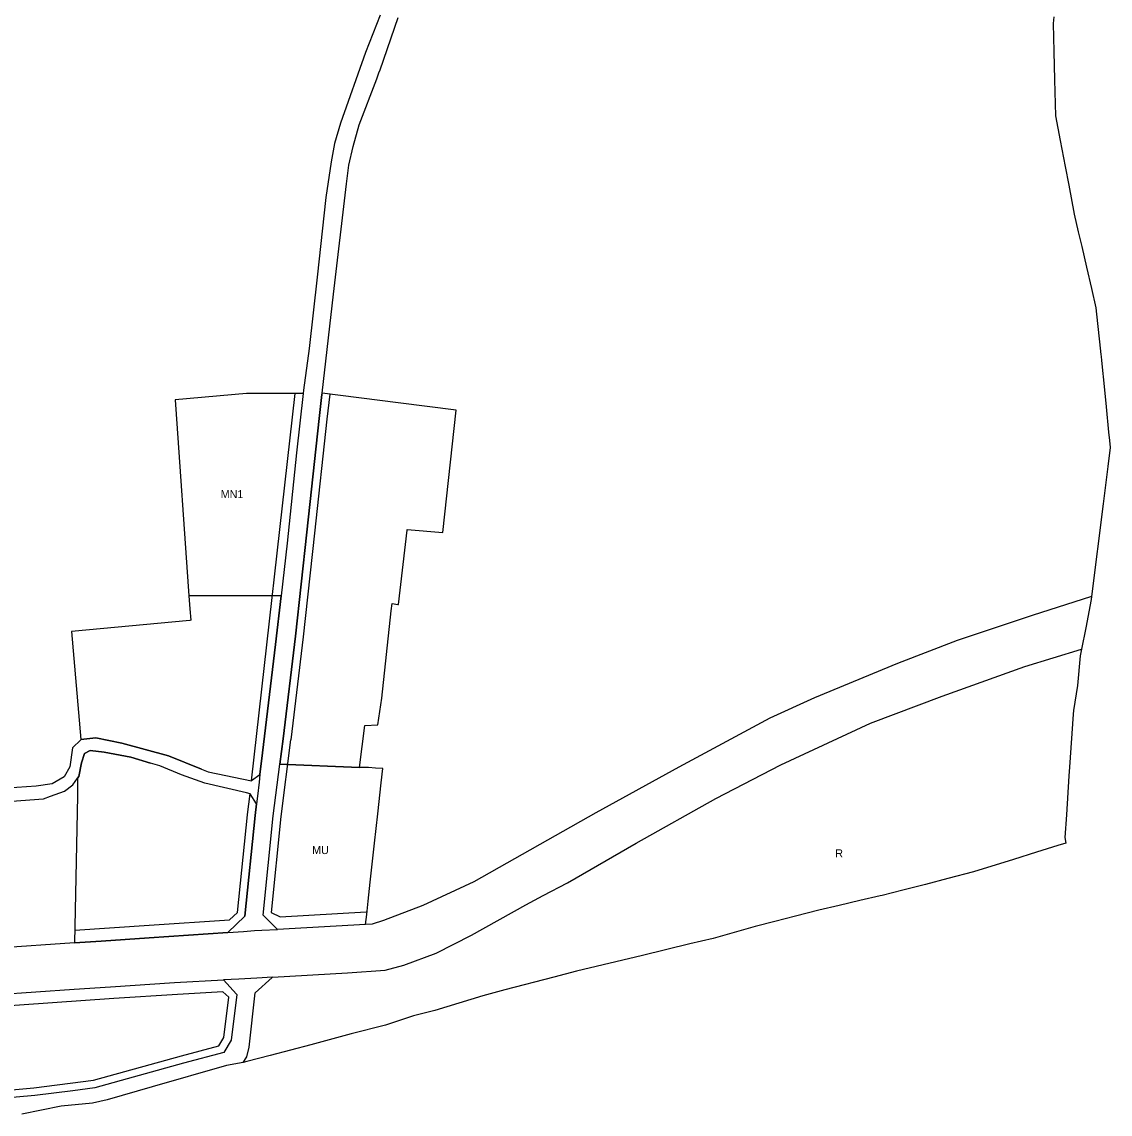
# Model space of a CAD drawing. Extents: x 7435758 to 7439981, y 5550649 to 5554049.
# Drawn here: x 7438816 to 7439523, y 5551109 to 5551818 of the extents above; entities that cross this region are included whole.
import ezdxf

# ---------------------------------------------------------------- set-up
doc = ezdxf.new("R2010")
doc.units = 0
for name, color, linetype in [('_Tereny_wyrok', 7, 'Continuous'), ('linie_rozgraniczające', 7, 'Continuous'), ('linie_zabudowy_nieprzekraczalne', 7, 'Continuous'), ('oznaczenia_przeznaczen', 7, 'Continuous')]:
    doc.layers.add(name, color=color, linetype=linetype)

msp = doc.modelspace()

# ---------------------------------------------------------------- linework, layer by layer
at = {"layer": '_Tereny_wyrok'}
for p, q in [((7439011.37, 5551576.2), (7439009.58, 5551560.59)), ((7439011.46, 5551576.97), (7439011.37, 5551576.2)), ((7439060.87, 5551570.69), (7439011.46, 5551576.97)), ((7439098.47, 5551565.91), (7439060.87, 5551570.69)), ((7439089.93, 5551486.51), (7439098.47, 5551565.91)), ((7439009.58, 5551560.59), (7439001.47, 5551486.59)), ((7439001.47, 5551486.59), (7438994.19, 5551419.2)), ((7439061.13, 5551439.6), (7439066.61, 5551488.08)), ((7439066.61, 5551488.08), (7439066.66, 5551488.5)), ((7439066.66, 5551488.5), (7439089.93, 5551486.51)), ((7438924.98, 5551445.38), (7438925.58, 5551436.89)), ((7438984.84, 5551445.28), (7438924.98, 5551445.38)), ((7438981.19, 5551413.78), (7438984.84, 5551445.28)), ((7438925.58, 5551436.89), (7438926.11, 5551429.43)), ((7439050.2, 5551378.72), (7439056.33, 5551435.64)), ((7439056.33, 5551435.64), (7439056.85, 5551440.41)), ((7439056.85, 5551440.41), (7439060.69, 5551439.68)), ((7439060.69, 5551439.68), (7439061.13, 5551439.6)), ((7438925.49, 5551429.38), (7438848.64, 5551422.1)), ((7438926.11, 5551429.43), (7438925.49, 5551429.38)), ((7438848.64, 5551422.1), (7438854.65, 5551351.92)), ((7438972.72, 5551343.24), (7438981.19, 5551413.78)), ((7438994.19, 5551419.2), (7438986.07, 5551352.33)), ((7439047.63, 5551361.46), (7439050.2, 5551378.72)), ((7439035.78, 5551333.81), (7439039.15, 5551361.12)), ((7439039.15, 5551361.12), (7439047.63, 5551361.46)), ((7438854.71, 5551351.86), (7438854.79, 5551351.94)), ((7438854.79, 5551351.94), (7438864.45, 5551353.08)), ((7438864.45, 5551353.08), (7438881.38, 5551349.66)), ((7438881.38, 5551349.66), (7438911.75, 5551341.38)), ((7438986.07, 5551352.33), (7438983.94, 5551335.93)), ((7438857.21, 5551342.9), (7438855.22, 5551336.85)), ((7438860.86, 5551344.91), (7438857.21, 5551342.9)), ((7438869.86, 5551343.79), (7438860.86, 5551344.91)), ((7438887.16, 5551340.38), (7438869.86, 5551343.79)), ((7438971.08, 5551329.11), (7438972.72, 5551343.24)), ((7438855.22, 5551336.85), (7438853.35, 5551327.82)), ((7438900.01, 5551336.59), (7438887.16, 5551340.38)), ((7438906.04, 5551334.81), (7438900.01, 5551336.59)), ((7438920.08, 5551329.04), (7438906.04, 5551334.81)), ((7438911.75, 5551341.38), (7438933.03, 5551332.71)), ((7438983.94, 5551335.93), (7439035.78, 5551333.81)), ((7438853.35, 5551327.82), (7438852.56, 5551326.73)), ((7438935.22, 5551323.68), (7438920.08, 5551329.04)), ((7438933.03, 5551332.71), (7438937.54, 5551330.86)), ((7438937.54, 5551330.86), (7438965.52, 5551325.2)), ((7438965.64, 5551325.25), (7438971.08, 5551329.11)), ((7438852.56, 5551326.73), (7438852.61, 5551315.53)), ((7438962.34, 5551317.32), (7438935.22, 5551323.68)), ((7438965.52, 5551325.2), (7438965.64, 5551325.25)), ((7438852.55, 5551315.4), (7438850.71, 5551219.79)), ((7438852.61, 5551315.53), (7438852.55, 5551315.4)), ((7438964.72, 5551316.6), (7438962.34, 5551317.32)), ((7438968.88, 5551310.16), (7438964.72, 5551316.6)), ((7438967.99, 5551302.55), (7438968.88, 5551310.16)), ((7438961.32, 5551237.2), (7438967.99, 5551302.55)), ((7438950.17, 5551226.55), (7438961.32, 5551237.2)), ((7438868, 5551220.94), (7438899.02, 5551223.06)), ((7438899.02, 5551223.06), (7438950.17, 5551226.55)), ((7438850.71, 5551219.79), (7438868, 5551220.94))]:
    msp.add_line(p, q, dxfattribs=at)
msp.add_lwpolyline([(7438854.65, 5551351.92), (7438854.71, 5551351.86)], dxfattribs=at)
at = {"layer": 'linie_rozgraniczające'}
for p, q in [((7439049.25, 5551822.61), (7439039.56, 5551798.25)), ((7439049.1, 5551787.07), (7439060.75, 5551821.16)), ((7439486.73, 5551821.61), (7439486.22, 5551817.3)), ((7439486.22, 5551817.3), (7439486.73, 5551798.99)), ((7439039.56, 5551798.25), (7439023.32, 5551752.4)), ((7439486.73, 5551798.99), (7439487.23, 5551780.67)), ((7439046.89, 5551781.28), (7439048.37, 5551785.17)), ((7439048.37, 5551785.17), (7439049.1, 5551787.07)), ((7439035.46, 5551751.39), (7439046.89, 5551781.28)), ((7439487.23, 5551780.67), (7439487.87, 5551757.21)), ((7439487.87, 5551757.21), (7439490.9, 5551741.18)), ((7439023.32, 5551752.4), (7439019.43, 5551739.22)), ((7439031.64, 5551737.24), (7439035.46, 5551751.39)), ((7439490.9, 5551741.18), (7439494.09, 5551724.26)), ((7439019.43, 5551739.22), (7439017.3, 5551727.41)), ((7439028.84, 5551725.06), (7439031.64, 5551737.24)), ((7439017.3, 5551727.41), (7439013.95, 5551704.23)), ((7439027.73, 5551716.53), (7439028.84, 5551725.06)), ((7439494.09, 5551724.26), (7439496.38, 5551712.14)), ((7439018.8, 5551641.23), (7439027.27, 5551713.06)), ((7439027.27, 5551713.06), (7439027.73, 5551716.53)), ((7439496.38, 5551712.14), (7439499.93, 5551693.34)), ((7439013.95, 5551704.23), (7439008.23, 5551652.42)), ((7439499.93, 5551693.34), (7439502.58, 5551681.92)), ((7439502.58, 5551681.92), (7439504.82, 5551672.32)), ((7439504.82, 5551672.32), (7439507.97, 5551658.81)), ((7439507.97, 5551658.81), (7439511.19, 5551644.92)), ((7439008.23, 5551652.42), (7439002.96, 5551605.98)), ((7439011.46, 5551576.97), (7439018.8, 5551641.23)), ((7439511.19, 5551644.92), (7439514.08, 5551632.52)), ((7439514.08, 5551632.52), (7439515.13, 5551622.21)), ((7439515.13, 5551622.21), (7439516.34, 5551610.41)), ((7439002.96, 5551605.98), (7438999.36, 5551579)), ((7439516.34, 5551610.41), (7439517.2, 5551602.06)), ((7439517.2, 5551602.06), (7439517.34, 5551600.76)), ((7439517.34, 5551600.76), (7439517.6, 5551598.21)), ((7439517.6, 5551598.21), (7439519.57, 5551579.27)), ((7438962.26, 5551576.72), (7438915.92, 5551572.56)), ((7438999.12, 5551576.76), (7438962.26, 5551576.72)), ((7438999.12, 5551576.76), (7438994.89, 5551538.32)), ((7438999.36, 5551579), (7438999.12, 5551576.76)), ((7439009.58, 5551560.59), (7439011.37, 5551576.2)), ((7439011.37, 5551576.2), (7439011.46, 5551576.97)), ((7439060.87, 5551570.69), (7439011.46, 5551576.97)), ((7439519.57, 5551579.27), (7439520.71, 5551568.08)), ((7438915.92, 5551572.56), (7438924.98, 5551445.38)), ((7439098.47, 5551565.91), (7439060.87, 5551570.69)), ((7439089.93, 5551486.51), (7439098.47, 5551565.91)), ((7439520.71, 5551568.08), (7439522.31, 5551551.62)), ((7439001.47, 5551486.59), (7439009.58, 5551560.59)), ((7439522.31, 5551551.62), (7439522.83, 5551546.28)), ((7439523.27, 5551541.74), (7439521.75, 5551529.36)), ((7439522.83, 5551546.28), (7439523.27, 5551541.74)), ((7438994.89, 5551538.32), (7438988.81, 5551479.6)), ((7439521.75, 5551529.36), (7439518.77, 5551505.17)), ((7439518.77, 5551505.13), (7439511.26, 5551444.8)), ((7439518.77, 5551505.17), (7439518.77, 5551505.13)), ((7438994.19, 5551419.2), (7439001.47, 5551486.59)), ((7439061.13, 5551439.6), (7439066.61, 5551488.08)), ((7439066.61, 5551488.08), (7439066.66, 5551488.5)), ((7439066.66, 5551488.5), (7439089.93, 5551486.51)), ((7438988.81, 5551479.6), (7438984.84, 5551445.28)), ((7438924.98, 5551445.38), (7438925.58, 5551436.89)), ((7438984.84, 5551445.28), (7438924.98, 5551445.38)), ((7438984.84, 5551445.28), (7438981.19, 5551413.78)), ((7439511.25, 5551444.79), (7439472.62, 5551432.62)), ((7439511.02, 5551442.9), (7439507.45, 5551424.59)), ((7439511.26, 5551444.8), (7439511.02, 5551442.9)), ((7439511.26, 5551444.8), (7439511.25, 5551444.79)), ((7438925.58, 5551436.89), (7438926.11, 5551429.43)), ((7439050.2, 5551378.72), (7439056.33, 5551435.64)), ((7439056.33, 5551435.64), (7439056.85, 5551440.41)), ((7439056.85, 5551440.41), (7439060.69, 5551439.68)), ((7439060.69, 5551439.68), (7439061.13, 5551439.6)), ((7438925.49, 5551429.38), (7438848.64, 5551422.1)), ((7438926.11, 5551429.43), (7438925.49, 5551429.38)), ((7439472.62, 5551432.62), (7439423.89, 5551416.23)), ((7438848.64, 5551422.1), (7438854.65, 5551351.92)), ((7439507.45, 5551424.59), (7439504.74, 5551410.66)), ((7438981.19, 5551413.78), (7438972.72, 5551343.24)), ((7438986.07, 5551352.33), (7438994.19, 5551419.2)), ((7439423.89, 5551416.23), (7439385.19, 5551401.28)), ((7439467.79, 5551399.49), (7439504.74, 5551410.66)), ((7439503.88, 5551406.28), (7439502.06, 5551387.04)), ((7439504.74, 5551410.66), (7439503.88, 5551406.28)), ((7439385.19, 5551401.28), (7439331.35, 5551378.93)), ((7439414.25, 5551380.03), (7439467.79, 5551399.49)), ((7439502.06, 5551387.04), (7439499.56, 5551370.7)), ((7439047.63, 5551361.46), (7439050.2, 5551378.72)), ((7439331.35, 5551378.93), (7439302.25, 5551365.81)), ((7439367.62, 5551362.5), (7439414.25, 5551380.03)), ((7439499.56, 5551370.7), (7439499.21, 5551368.43)), ((7439302.25, 5551365.81), (7439243.24, 5551333.99)), ((7439499.21, 5551368.43), (7439496.9, 5551334.03)), ((7439035.78, 5551333.81), (7439039.15, 5551361.12)), ((7439039.15, 5551361.12), (7439047.63, 5551361.46)), ((7439309.45, 5551335.44), (7439367.62, 5551362.5)), ((7438854.66, 5551351.81), (7438849.42, 5551346.5)), ((7438854.79, 5551351.94), (7438854.66, 5551351.81)), ((7438864.45, 5551353.08), (7438854.79, 5551351.94)), ((7438881.38, 5551349.66), (7438864.45, 5551353.08)), ((7438911.75, 5551341.38), (7438881.38, 5551349.66)), ((7438983.94, 5551335.93), (7438986.07, 5551352.33)), ((7438849.42, 5551346.5), (7438847.68, 5551334.12)), ((7438855.22, 5551336.85), (7438857.21, 5551342.9)), ((7438857.21, 5551342.9), (7438860.86, 5551344.91)), ((7438860.86, 5551344.91), (7438869.86, 5551343.79)), ((7438869.86, 5551343.79), (7438887.16, 5551340.38)), ((7438972.72, 5551343.24), (7438971.08, 5551329.11)), ((7438853.35, 5551327.82), (7438855.22, 5551336.85)), ((7438887.16, 5551340.38), (7438900.01, 5551336.59)), ((7438906.04, 5551334.81), (7438900.01, 5551336.59)), ((7438920.08, 5551329.04), (7438906.04, 5551334.81)), ((7438933.03, 5551332.71), (7438911.75, 5551341.38)), ((7438979.59, 5551302.4), (7438983.94, 5551335.93)), ((7439035.78, 5551333.81), (7438983.94, 5551335.93)), ((7439267.12, 5551313.55), (7439309.45, 5551335.44)), ((7438843.84, 5551327.62), (7438836.19, 5551323.21)), ((7438847.68, 5551334.12), (7438843.84, 5551327.62)), ((7438852.56, 5551326.73), (7438853.35, 5551327.82)), ((7438935.22, 5551323.68), (7438920.08, 5551329.04)), ((7438933.03, 5551332.71), (7438937.54, 5551330.86)), ((7438937.54, 5551330.86), (7438965.52, 5551325.2)), ((7438965.64, 5551325.25), (7438971.08, 5551329.11)), ((7438971.08, 5551329.11), (7438970.51, 5551324.19)), ((7439041.62, 5551333.66), (7439035.78, 5551333.81)), ((7439046.18, 5551333.38), (7439041.62, 5551333.66)), ((7439050.87, 5551333.09), (7439046.18, 5551333.38)), ((7439049.86, 5551323.88), (7439050.87, 5551333.09)), ((7439243.24, 5551333.99), (7439189.29, 5551304.22)), ((7439496.52, 5551328.38), (7439494.82, 5551302.97)), ((7439496.9, 5551334.03), (7439496.52, 5551328.38)), ((7438825.8, 5551321.67), (7438799.39, 5551319.85)), ((7438836.19, 5551323.21), (7438825.8, 5551321.67)), ((7438844.03, 5551318.49), (7438849.46, 5551322.44)), ((7438849.46, 5551322.44), (7438852.56, 5551326.73)), ((7438852.56, 5551326.73), (7438852.61, 5551315.53)), ((7438962.34, 5551317.32), (7438935.22, 5551323.68)), ((7438965.52, 5551325.2), (7438965.64, 5551325.25)), ((7438970.51, 5551324.19), (7438969.46, 5551315.18)), ((7439047.62, 5551303.62), (7439049.86, 5551323.88)), ((7438809.97, 5551311.88), (7438830.43, 5551313.46)), ((7438830.43, 5551313.46), (7438835.09, 5551315.18)), ((7438835.09, 5551315.18), (7438844.03, 5551318.49)), ((7438852.55, 5551315.4), (7438850.71, 5551219.79)), ((7438852.61, 5551315.53), (7438852.55, 5551315.4)), ((7438964.72, 5551316.6), (7438962.34, 5551317.32)), ((7438968.85, 5551310.23), (7438964.72, 5551316.6)), ((7438969.46, 5551315.18), (7438968.88, 5551310.16)), ((7439215.4, 5551284.5), (7439267.12, 5551313.55)), ((7438968.88, 5551310.16), (7438967.99, 5551302.55)), ((7438968.88, 5551310.16), (7438968.85, 5551310.23)), ((7438967.99, 5551302.55), (7438961.32, 5551237.2)), ((7438973.26, 5551237.8), (7438979.59, 5551302.4)), ((7439045.53, 5551284.64), (7439047.62, 5551303.62)), ((7439189.29, 5551304.22), (7439110.02, 5551259.43)), ((7439494.82, 5551302.97), (7439493.84, 5551288.34)), ((7439493.84, 5551288.34), (7439494.42, 5551284.61)), ((7439042.73, 5551259.23), (7439045.53, 5551284.64)), ((7439170.76, 5551258.81), (7439215.4, 5551284.5)), ((7439475.49, 5551278.79), (7439460.6, 5551273.99)), ((7439489.34, 5551283.08), (7439475.49, 5551278.79)), ((7439494.42, 5551284.61), (7439489.34, 5551283.08)), ((7439460.6, 5551273.99), (7439434.49, 5551265.95)), ((7439434.49, 5551265.95), (7439417.92, 5551261.67)), ((7439041.38, 5551246.96), (7439042.73, 5551259.23)), ((7439110.02, 5551259.43), (7439076.89, 5551244.09)), ((7439155.05, 5551250.51), (7439170.76, 5551258.81)), ((7439403.43, 5551257.64), (7439388.72, 5551253.97)), ((7439417.92, 5551261.67), (7439403.43, 5551257.64)), ((7439143.76, 5551244.54), (7439155.05, 5551250.51)), ((7439373.86, 5551250.37), (7439360.72, 5551247.3)), ((7439375.19, 5551250.68), (7439373.86, 5551250.37)), ((7439388.72, 5551253.97), (7439375.19, 5551250.68)), ((7439040.4, 5551238.14), (7439041.38, 5551246.96)), ((7439076.89, 5551244.09), (7439051.35, 5551234.41)), ((7439108.54, 5551224.8), (7439143.76, 5551244.54)), ((7439347.2, 5551244), (7439334.05, 5551241.13)), ((7439360.72, 5551247.3), (7439347.2, 5551244)), ((7438961.32, 5551237.2), (7438950.17, 5551226.55)), ((7438982.38, 5551228.55), (7438973.26, 5551237.8)), ((7439039.69, 5551231.7), (7439040.4, 5551238.14)), ((7439318.91, 5551237.21), (7439305.54, 5551233.8)), ((7439334.05, 5551241.13), (7439318.91, 5551237.21)), ((7438972.3, 5551228), (7438982.38, 5551228.55)), ((7439039.69, 5551231.7), (7438982.38, 5551228.55)), ((7439043.9, 5551231.93), (7439039.69, 5551231.7)), ((7439051.35, 5551234.41), (7439043.9, 5551231.93)), ((7439292.79, 5551230.48), (7439265.43, 5551222.61)), ((7439305.54, 5551233.8), (7439292.79, 5551230.48)), ((7438899.02, 5551223.06), (7438868, 5551220.94)), ((7438950.17, 5551226.55), (7438899.02, 5551223.06)), ((7438950.17, 5551226.55), (7438960.3, 5551227.24)), ((7438960.3, 5551227.24), (7438967.6, 5551227.74)), ((7438967.6, 5551227.74), (7438972.3, 5551228)), ((7439085.55, 5551213.16), (7439108.54, 5551224.8)), ((7439265.43, 5551222.61), (7439250.31, 5551219.11)), ((7438850.71, 5551219.79), (7438735.34, 5551212.15)), ((7438868, 5551220.94), (7438850.71, 5551219.79)), ((7439250.31, 5551219.11), (7439219.61, 5551211.6)), ((7439064.47, 5551205.31), (7439085.55, 5551213.16)), ((7439219.61, 5551211.6), (7439176.71, 5551201.4)), ((7438979.16, 5551197.55), (7439027.83, 5551200.3)), ((7439027.83, 5551200.3), (7439052.32, 5551202.01)), ((7439052.32, 5551202.01), (7439064.47, 5551205.31)), ((7439176.71, 5551201.4), (7439161.92, 5551197.44)), ((7438874.07, 5551191.3), (7438915.54, 5551193.96)), ((7438915.54, 5551193.96), (7438947.41, 5551195.76)), ((7438957.27, 5551196.32), (7438947.41, 5551195.76)), ((7438947.41, 5551195.76), (7438955.93, 5551186.41)), ((7438969.02, 5551196.98), (7438957.27, 5551196.32)), ((7438967.95, 5551187.31), (7438979.01, 5551197.39)), ((7438979.16, 5551197.55), (7438969.02, 5551196.98)), ((7438979.01, 5551197.39), (7438979.16, 5551197.55)), ((7439161.92, 5551197.44), (7439130.16, 5551189.28)), ((7438754.39, 5551183.04), (7438850.43, 5551189.67)), ((7438850.43, 5551189.67), (7438874.07, 5551191.3)), ((7438956.05, 5551186.35), (7438952.39, 5551156.54)), ((7438955.93, 5551186.41), (7438956.05, 5551186.35)), ((7438964.02, 5551151.95), (7438967.95, 5551187.31)), ((7439130.16, 5551189.28), (7439115.82, 5551185.47)), ((7439115.82, 5551185.47), (7439084.67, 5551175.85)), ((7439070.8, 5551172.49), (7439052.63, 5551166.35)), ((7439084.67, 5551175.85), (7439070.8, 5551172.49)), ((7439052.63, 5551166.35), (7439030.35, 5551160.62)), ((7439030.35, 5551160.62), (7439004.13, 5551153.45)), ((7438952.39, 5551156.54), (7438947.58, 5551148.65)), ((7438962.6, 5551145.73), (7438964.02, 5551151.95)), ((7439004.13, 5551153.45), (7438977.77, 5551146.59)), ((7438947.58, 5551148.65), (7438921.37, 5551141.6)), ((7438960.11, 5551142.17), (7438962.6, 5551145.73)), ((7438977.77, 5551146.59), (7438962.48, 5551142.62)), ((7438921.37, 5551141.6), (7438863.9, 5551125.6)), ((7438949.34, 5551140.13), (7438901.06, 5551126.16)), ((7438960.11, 5551142.17), (7438949.34, 5551140.13)), ((7438962.48, 5551142.62), (7438960.11, 5551142.17)), ((7438849.53, 5551123.76), (7438824.79, 5551120.59)), ((7438863.9, 5551125.6), (7438849.53, 5551123.76)), ((7438901.06, 5551126.16), (7438871.92, 5551117.84)), ((7438824.79, 5551120.59), (7438790.72, 5551117.67)), ((7438862.3, 5551115.55), (7438841.9, 5551113.64)), ((7438871.92, 5551117.84), (7438862.3, 5551115.55)), ((7438841.9, 5551113.64), (7438816.43, 5551108.51))]:
    msp.add_line(p, q, dxfattribs=at)
at = {"layer": 'linie_zabudowy_nieprzekraczalne'}
for points in [[(7438965.52, 5551325.2), (7438994.05, 5551576.76)], [(7439016.42, 5551576.34), (7439014.55, 5551560.04), (7439006.44, 5551486.04), (7438999.16, 5551418.66), (7438999.16, 5551418.6), (7438991.03, 5551351.72), (7438991.02, 5551351.68), (7438984.55, 5551301.83), (7438978.46, 5551239.64), (7438984.23, 5551236.79), (7439040.16, 5551239.87)], [(7438850.87, 5551228.05), (7438899.09, 5551231.31), (7438951.29, 5551234.7), (7438956.53, 5551239.54), (7438963.02, 5551303.06), (7438963.03, 5551303.13), (7438964.72, 5551316.6)], [(7438790.4, 5551122.66), (7438824.25, 5551125.56), (7438862.91, 5551130.51), (7438920.03, 5551146.42), (7438920.07, 5551146.43), (7438944.36, 5551152.96), (7438947.56, 5551158.22), (7438950.8, 5551184.62), (7438947.07, 5551187.9), (7438917.58, 5551186.24), (7438876.16, 5551183.58), (7438756.48, 5551175.32)]]:
    msp.add_lwpolyline(points, dxfattribs=at)

# ---------------------------------------------------------------- texts
at = {"layer": 'oznaczenia_przeznaczen'}
for s, p in [('MN1', (7438945.6, 5551508.78)), ('MU', (7439004.96, 5551277.5)), ('R', (7439344.74, 5551275.38))]:
    msp.add_text(s, height=5.2, dxfattribs=at).set_placement(p)

doc.saveas('drawing.dxf')
